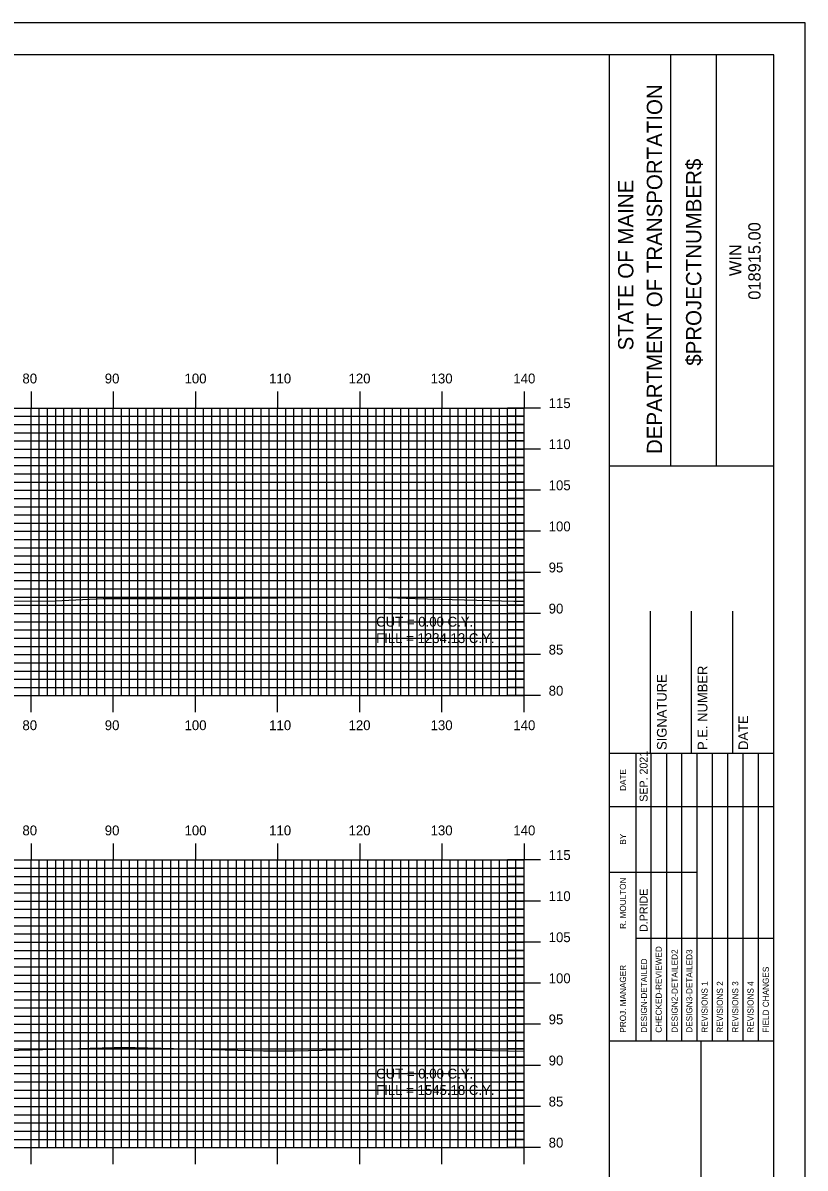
# Model space of a CAD drawing. Extents: x 879 to 1222, y -1658 to -1438.
# Drawn here: x 1123.7 to 1218.9, y -1577.1 to -1437.7 of the extents above; entities that cross this region are included whole.
import ezdxf

# ---------------------------------------------------------------- set-up
doc = ezdxf.new("R2010")
doc.units = 0
for name, color, linetype in [('BORDER', 7, 'Continuous'), ('D_Text_Standard', 7, 'Continuous'), ('H_V ANNOTATION', 7, 'Continuous'), ('MAJOR', 7, 'Continuous'), ('MINOR', 7, 'Continuous'), ('PLOT BOUNDARY', 7, 'Continuous'), ('S_Roadway_Centerline', 7, 'Continuous')]:
    doc.layers.add(name, color=color, linetype=linetype)

msp = doc.modelspace()

# ---------------------------------------------------------------- linework, layer by layer
at = {"layer": 'BORDER'}
for p, q in [((1195.05, -1651.6), (1195.05, -1441.6)), ((1202.5, -1491.61), (1202.5, -1441.61)), ((1208.09, -1491.61), (1208.09, -1441.61)), ((1195.05, -1491.62), (1215.05, -1491.62)), ((1200.05, -1526.6), (1200.05, -1509.3)), ((1205.05, -1526.6), (1205.05, -1509.3)), ((1210.05, -1526.6), (1210.05, -1509.3)), ((1195.05, -1526.6), (1215.05, -1526.6)), ((1195.05, -1561.6), (1215.05, -1561.6)), ((1206.23, -1631.6), (1206.23, -1561.6))]:
    msp.add_line(p, q, dxfattribs=at)
msp.add_lwpolyline([(895.05, -1651.6), (1215.05, -1651.6), (1215.05, -1441.6), (895.05, -1441.6)], close=True, dxfattribs=at)
for points in [[(1198.28, -1533.1), (1198.28, -1526.6)], [(1200.14, -1561.59), (1200.14, -1526.6)], [(1202.01, -1526.6), (1202.01, -1561.59)], [(1203.87, -1561.59), (1203.87, -1526.6)], [(1205.73, -1561.59), (1205.73, -1526.6)], [(1207.6, -1561.59), (1207.6, -1526.6)], [(1209.46, -1561.59), (1209.46, -1526.6)], [(1211.32, -1561.59), (1211.32, -1526.6)], [(1213.19, -1561.59), (1213.19, -1526.6)], [(1198.28, -1561.59), (1198.28, -1528.01)], [(1195.05, -1533.1), (1215.05, -1533.1)], [(1195.05, -1541.1), (1198.28, -1541.1)], [(1198.28, -1541.1), (1205.73, -1541.1)], [(1198.28, -1549.1), (1215.05, -1549.1)]]:
    msp.add_lwpolyline(points, dxfattribs=at)
at = {"layer": 'MAJOR'}
for p, q in [((1124.65, -1482.6), (1124.65, -1484.6)), ((1134.65, -1482.6), (1134.65, -1484.6)), ((1144.65, -1482.6), (1144.65, -1484.6)), ((1154.65, -1482.6), (1154.65, -1484.6)), ((1164.65, -1482.6), (1164.65, -1484.6)), ((1174.65, -1482.6), (1174.65, -1484.6)), ((1184.65, -1482.6), (1184.65, -1484.6)), ((904.65, -1484.6), (1184.65, -1484.6)), ((904.65, -1484.6), (1184.65, -1484.6)), ((1124.65, -1519.6), (1124.65, -1484.6)), ((1134.65, -1519.6), (1134.65, -1484.6)), ((1144.65, -1519.6), (1144.65, -1484.6)), ((1154.65, -1519.6), (1154.65, -1484.6)), ((1164.65, -1519.6), (1164.65, -1484.6)), ((1174.65, -1519.6), (1174.65, -1484.6)), ((1186.65, -1484.6), (1182.64, -1484.6)), ((1184.65, -1519.6), (1184.65, -1484.6)), ((1184.65, -1519.6), (1184.65, -1484.6)), ((904.65, -1489.6), (1184.65, -1489.6)), ((1186.65, -1489.6), (1182.64, -1489.6)), ((904.65, -1494.6), (1184.65, -1494.6)), ((1186.65, -1494.6), (1182.64, -1494.6)), ((904.65, -1499.6), (1184.65, -1499.6)), ((1186.65, -1499.6), (1182.64, -1499.6)), ((904.65, -1504.6), (1184.65, -1504.6)), ((1186.65, -1504.6), (1182.64, -1504.6)), ((904.65, -1509.6), (1184.65, -1509.6)), ((1186.65, -1509.6), (1182.64, -1509.6)), ((904.65, -1514.6), (1184.65, -1514.6)), ((1186.65, -1514.6), (1182.64, -1514.6)), ((904.65, -1519.6), (1184.65, -1519.6)), ((904.65, -1519.6), (1184.65, -1519.6)), ((1124.65, -1521.61), (1124.65, -1519.6)), ((1134.65, -1521.61), (1134.65, -1519.6)), ((1144.65, -1521.61), (1144.65, -1519.6)), ((1154.65, -1521.61), (1154.65, -1519.6)), ((1164.65, -1521.61), (1164.65, -1519.6)), ((1174.65, -1521.61), (1174.65, -1519.6)), ((1186.65, -1519.6), (1182.64, -1519.6)), ((1184.65, -1521.61), (1184.65, -1519.6)), ((1124.65, -1537.6), (1124.65, -1539.6)), ((1134.65, -1537.6), (1134.65, -1539.6)), ((1144.65, -1537.6), (1144.65, -1539.6)), ((1154.65, -1537.6), (1154.65, -1539.6)), ((1164.65, -1537.6), (1164.65, -1539.6)), ((1174.65, -1537.6), (1174.65, -1539.6)), ((1184.65, -1537.6), (1184.65, -1539.6)), ((904.65, -1539.6), (1184.65, -1539.6)), ((904.65, -1539.6), (1184.65, -1539.6)), ((1124.65, -1574.6), (1124.65, -1539.6)), ((1134.65, -1574.6), (1134.65, -1539.6)), ((1144.65, -1574.6), (1144.65, -1539.6)), ((1154.65, -1574.6), (1154.65, -1539.6)), ((1164.65, -1574.6), (1164.65, -1539.6)), ((1174.65, -1574.6), (1174.65, -1539.6)), ((1186.65, -1539.6), (1182.64, -1539.6)), ((1184.65, -1574.6), (1184.65, -1539.6)), ((1184.65, -1574.6), (1184.65, -1539.6)), ((904.65, -1544.6), (1184.65, -1544.6)), ((1186.65, -1544.6), (1182.64, -1544.6)), ((904.65, -1549.6), (1184.65, -1549.6)), ((1186.65, -1549.6), (1182.64, -1549.6)), ((904.65, -1554.6), (1184.65, -1554.6)), ((1186.65, -1554.6), (1182.64, -1554.6)), ((904.65, -1559.6), (1184.65, -1559.6)), ((1186.65, -1559.6), (1182.64, -1559.6)), ((904.65, -1564.6), (1184.65, -1564.6)), ((1186.65, -1564.6), (1182.64, -1564.6)), ((904.65, -1569.6), (1184.65, -1569.6)), ((1186.65, -1569.6), (1182.64, -1569.6)), ((904.65, -1574.6), (1184.65, -1574.6)), ((904.65, -1574.6), (1184.65, -1574.6)), ((1124.65, -1576.61), (1124.65, -1574.6)), ((1134.65, -1576.61), (1134.65, -1574.6)), ((1144.65, -1576.61), (1144.65, -1574.6)), ((1154.65, -1576.61), (1154.65, -1574.6)), ((1164.65, -1576.61), (1164.65, -1574.6)), ((1174.65, -1576.61), (1174.65, -1574.6)), ((1186.65, -1574.6), (1182.64, -1574.6)), ((1184.65, -1576.61), (1184.65, -1574.6))]:
    msp.add_line(p, q, dxfattribs=at)
at = {"layer": 'MINOR'}
for p, q in [((904.65, -1485.6), (1184.65, -1485.6)), ((1125.65, -1519.6), (1125.65, -1484.6)), ((1126.65, -1519.6), (1126.65, -1484.6)), ((1127.65, -1519.6), (1127.65, -1484.6)), ((1128.65, -1519.6), (1128.65, -1484.6)), ((1129.65, -1519.6), (1129.65, -1484.6)), ((1130.65, -1519.6), (1130.65, -1484.6)), ((1131.65, -1519.6), (1131.65, -1484.6)), ((1132.65, -1519.6), (1132.65, -1484.6)), ((1133.65, -1519.6), (1133.65, -1484.6)), ((1135.65, -1519.6), (1135.65, -1484.6)), ((1136.65, -1519.6), (1136.65, -1484.6)), ((1137.65, -1519.6), (1137.65, -1484.6)), ((1138.65, -1519.6), (1138.65, -1484.6)), ((1139.65, -1519.6), (1139.65, -1484.6)), ((1140.65, -1519.6), (1140.65, -1484.6)), ((1141.65, -1519.6), (1141.65, -1484.6)), ((1142.65, -1519.6), (1142.65, -1484.6)), ((1143.65, -1519.6), (1143.65, -1484.6)), ((1145.65, -1519.6), (1145.65, -1484.6)), ((1146.65, -1519.6), (1146.65, -1484.6)), ((1147.65, -1519.6), (1147.65, -1484.6)), ((1148.65, -1519.6), (1148.65, -1484.6)), ((1149.65, -1519.6), (1149.65, -1484.6)), ((1150.65, -1519.6), (1150.65, -1484.6)), ((1151.65, -1519.6), (1151.65, -1484.6)), ((1152.65, -1519.6), (1152.65, -1484.6)), ((1153.65, -1519.6), (1153.65, -1484.6)), ((1155.65, -1519.6), (1155.65, -1484.6)), ((1156.65, -1519.6), (1156.65, -1484.6)), ((1157.65, -1519.6), (1157.65, -1484.6)), ((1158.65, -1519.6), (1158.65, -1484.6)), ((1159.65, -1519.6), (1159.65, -1484.6)), ((1160.65, -1519.6), (1160.65, -1484.6)), ((1161.65, -1519.6), (1161.65, -1484.6)), ((1162.65, -1519.6), (1162.65, -1484.6)), ((1163.65, -1519.6), (1163.65, -1484.6)), ((1165.65, -1519.6), (1165.65, -1484.6)), ((1166.65, -1519.6), (1166.65, -1484.6)), ((1167.65, -1519.6), (1167.65, -1484.6)), ((1168.65, -1519.6), (1168.65, -1484.6)), ((1169.65, -1519.6), (1169.65, -1484.6)), ((1170.65, -1519.6), (1170.65, -1484.6)), ((1171.65, -1519.6), (1171.65, -1484.6)), ((1172.65, -1519.6), (1172.65, -1484.6)), ((1173.65, -1519.6), (1173.65, -1484.6)), ((1175.65, -1519.6), (1175.65, -1484.6)), ((1176.65, -1519.6), (1176.65, -1484.6)), ((1177.65, -1519.6), (1177.65, -1484.6)), ((1178.65, -1519.6), (1178.65, -1484.6)), ((1179.65, -1519.6), (1179.65, -1484.6)), ((1180.65, -1519.6), (1180.65, -1484.6)), ((1181.65, -1519.6), (1181.65, -1484.6)), ((1184.65, -1485.6), (1182.64, -1485.6)), ((1182.65, -1519.6), (1182.65, -1484.6)), ((1183.65, -1519.6), (1183.65, -1484.6)), ((904.65, -1486.6), (1184.65, -1486.6)), ((1184.65, -1486.6), (1182.64, -1486.6)), ((904.65, -1487.6), (1184.65, -1487.6)), ((1184.65, -1487.6), (1182.64, -1487.6)), ((904.65, -1488.6), (1184.65, -1488.6)), ((1184.65, -1488.6), (1182.64, -1488.6)), ((904.65, -1490.6), (1184.65, -1490.6)), ((1184.65, -1490.6), (1182.64, -1490.6)), ((904.65, -1491.6), (1184.65, -1491.6)), ((904.65, -1492.6), (1184.65, -1492.6)), ((1184.65, -1491.6), (1182.64, -1491.6)), ((1184.65, -1492.6), (1182.64, -1492.6)), ((904.65, -1493.6), (1184.65, -1493.6)), ((1184.65, -1493.6), (1182.64, -1493.6)), ((904.65, -1495.6), (1184.65, -1495.6)), ((904.65, -1496.6), (1184.65, -1496.6)), ((1184.65, -1495.6), (1182.64, -1495.6)), ((1184.65, -1496.6), (1182.64, -1496.6)), ((904.65, -1497.6), (1184.65, -1497.6)), ((1184.65, -1497.6), (1182.64, -1497.6)), ((904.65, -1498.6), (1184.65, -1498.6)), ((1184.65, -1498.6), (1182.64, -1498.6)), ((904.65, -1500.6), (1184.65, -1500.6)), ((1184.65, -1500.6), (1182.64, -1500.6)), ((904.65, -1501.6), (1184.65, -1501.6)), ((1184.65, -1501.6), (1182.64, -1501.6)), ((904.65, -1502.6), (1184.65, -1502.6)), ((904.65, -1503.6), (1184.65, -1503.6)), ((1184.65, -1502.6), (1182.64, -1502.6)), ((1184.65, -1503.6), (1182.64, -1503.6)), ((904.65, -1505.6), (1184.65, -1505.6)), ((904.65, -1506.6), (1184.65, -1506.6)), ((1184.65, -1505.6), (1182.64, -1505.6)), ((1184.65, -1506.6), (1182.64, -1506.6)), ((904.65, -1507.6), (1184.65, -1507.6)), ((1184.65, -1507.6), (1182.64, -1507.6)), ((904.65, -1508.6), (1184.65, -1508.6)), ((1184.65, -1508.6), (1182.64, -1508.6)), ((904.65, -1510.6), (1184.65, -1510.6)), ((1184.65, -1510.6), (1182.64, -1510.6)), ((904.65, -1511.6), (1184.65, -1511.6)), ((1184.65, -1511.6), (1182.64, -1511.6)), ((904.65, -1512.6), (1184.65, -1512.6)), ((904.65, -1513.6), (1184.65, -1513.6)), ((1184.65, -1512.6), (1182.64, -1512.6)), ((1184.65, -1513.6), (1182.64, -1513.6)), ((904.65, -1515.6), (1184.65, -1515.6)), ((1184.65, -1515.6), (1182.64, -1515.6)), ((904.65, -1516.6), (1184.65, -1516.6)), ((904.65, -1517.6), (1184.65, -1517.6)), ((1184.65, -1516.6), (1182.64, -1516.6)), ((1184.65, -1517.6), (1182.64, -1517.6)), ((904.65, -1518.6), (1184.65, -1518.6)), ((1184.65, -1518.6), (1182.64, -1518.6)), ((1125.65, -1574.6), (1125.65, -1539.6)), ((1126.65, -1574.6), (1126.65, -1539.6)), ((1127.65, -1574.6), (1127.65, -1539.6)), ((1128.65, -1574.6), (1128.65, -1539.6)), ((1129.65, -1574.6), (1129.65, -1539.6)), ((1130.65, -1574.6), (1130.65, -1539.6)), ((1131.65, -1574.6), (1131.65, -1539.6)), ((1132.65, -1574.6), (1132.65, -1539.6)), ((1133.65, -1574.6), (1133.65, -1539.6)), ((1135.65, -1574.6), (1135.65, -1539.6)), ((1136.65, -1574.6), (1136.65, -1539.6)), ((1137.65, -1574.6), (1137.65, -1539.6)), ((1138.65, -1574.6), (1138.65, -1539.6)), ((1139.65, -1574.6), (1139.65, -1539.6)), ((1140.65, -1574.6), (1140.65, -1539.6)), ((1141.65, -1574.6), (1141.65, -1539.6)), ((1142.65, -1574.6), (1142.65, -1539.6)), ((1143.65, -1574.6), (1143.65, -1539.6)), ((1145.65, -1574.6), (1145.65, -1539.6)), ((1146.65, -1574.6), (1146.65, -1539.6)), ((1147.65, -1574.6), (1147.65, -1539.6)), ((1148.65, -1574.6), (1148.65, -1539.6)), ((1149.65, -1574.6), (1149.65, -1539.6)), ((1150.65, -1574.6), (1150.65, -1539.6)), ((1151.65, -1574.6), (1151.65, -1539.6)), ((1152.65, -1574.6), (1152.65, -1539.6)), ((1153.65, -1574.6), (1153.65, -1539.6)), ((1155.65, -1574.6), (1155.65, -1539.6)), ((1156.65, -1574.6), (1156.65, -1539.6)), ((1157.65, -1574.6), (1157.65, -1539.6)), ((1158.65, -1574.6), (1158.65, -1539.6)), ((1159.65, -1574.6), (1159.65, -1539.6)), ((1160.65, -1574.6), (1160.65, -1539.6)), ((1161.65, -1574.6), (1161.65, -1539.6)), ((1162.65, -1574.6), (1162.65, -1539.6)), ((1163.65, -1574.6), (1163.65, -1539.6)), ((1165.65, -1574.6), (1165.65, -1539.6)), ((1166.65, -1574.6), (1166.65, -1539.6)), ((1167.65, -1574.6), (1167.65, -1539.6)), ((1168.65, -1574.6), (1168.65, -1539.6)), ((1169.65, -1574.6), (1169.65, -1539.6)), ((1170.65, -1574.6), (1170.65, -1539.6)), ((1171.65, -1574.6), (1171.65, -1539.6)), ((1172.65, -1574.6), (1172.65, -1539.6)), ((1173.65, -1574.6), (1173.65, -1539.6)), ((1175.65, -1574.6), (1175.65, -1539.6)), ((1176.65, -1574.6), (1176.65, -1539.6)), ((1177.65, -1574.6), (1177.65, -1539.6)), ((1178.65, -1574.6), (1178.65, -1539.6)), ((1179.65, -1574.6), (1179.65, -1539.6)), ((1180.65, -1574.6), (1180.65, -1539.6)), ((1181.65, -1574.6), (1181.65, -1539.6)), ((1182.65, -1574.6), (1182.65, -1539.6)), ((1183.65, -1574.6), (1183.65, -1539.6)), ((904.65, -1540.6), (1184.65, -1540.6)), ((1184.65, -1540.6), (1182.64, -1540.6)), ((904.65, -1541.6), (1184.65, -1541.6)), ((904.65, -1542.6), (1184.65, -1542.6)), ((1184.65, -1541.6), (1182.64, -1541.6)), ((1184.65, -1542.6), (1182.64, -1542.6)), ((904.65, -1543.6), (1184.65, -1543.6)), ((1184.65, -1543.6), (1182.64, -1543.6)), ((904.65, -1545.6), (1184.65, -1545.6)), ((1184.65, -1545.6), (1182.64, -1545.6)), ((904.65, -1546.6), (1184.65, -1546.6)), ((1184.65, -1546.6), (1182.64, -1546.6)), ((904.65, -1547.6), (1184.65, -1547.6)), ((1184.65, -1547.6), (1182.64, -1547.6)), ((904.65, -1548.6), (1184.65, -1548.6)), ((1184.65, -1548.6), (1182.64, -1548.6)), ((904.65, -1550.6), (1184.65, -1550.6)), ((1184.65, -1550.6), (1182.64, -1550.6)), ((904.65, -1551.6), (1184.65, -1551.6)), ((904.65, -1552.6), (1184.65, -1552.6)), ((1184.65, -1551.6), (1182.64, -1551.6)), ((1184.65, -1552.6), (1182.64, -1552.6)), ((904.65, -1553.6), (1184.65, -1553.6)), ((1184.65, -1553.6), (1182.64, -1553.6)), ((904.65, -1555.6), (1184.65, -1555.6)), ((904.65, -1556.6), (1184.65, -1556.6)), ((1184.65, -1555.6), (1182.64, -1555.6)), ((1184.65, -1556.6), (1182.64, -1556.6)), ((904.65, -1557.6), (1184.65, -1557.6)), ((1184.65, -1557.6), (1182.64, -1557.6)), ((904.65, -1558.6), (1184.65, -1558.6)), ((1184.65, -1558.6), (1182.64, -1558.6)), ((904.65, -1560.6), (1184.65, -1560.6)), ((1184.65, -1560.6), (1182.64, -1560.6)), ((904.65, -1561.6), (1184.65, -1561.6)), ((1184.65, -1561.6), (1182.64, -1561.6)), ((904.65, -1562.6), (1184.65, -1562.6)), ((904.65, -1563.6), (1184.65, -1563.6)), ((1184.65, -1562.6), (1182.64, -1562.6)), ((1184.65, -1563.6), (1182.64, -1563.6)), ((904.65, -1565.6), (1184.65, -1565.6)), ((1184.65, -1565.6), (1182.64, -1565.6)), ((904.65, -1566.6), (1184.65, -1566.6)), ((904.65, -1567.6), (1184.65, -1567.6)), ((1184.65, -1566.6), (1182.64, -1566.6)), ((1184.65, -1567.6), (1182.64, -1567.6)), ((904.65, -1568.6), (1184.65, -1568.6)), ((1184.65, -1568.6), (1182.64, -1568.6)), ((904.65, -1570.6), (1184.65, -1570.6)), ((1184.65, -1570.6), (1182.64, -1570.6)), ((904.65, -1571.6), (1184.65, -1571.6)), ((1184.65, -1571.6), (1182.64, -1571.6)), ((904.65, -1572.6), (1184.65, -1572.6)), ((1184.65, -1572.6), (1182.64, -1572.6)), ((904.65, -1573.6), (1184.65, -1573.6)), ((1184.65, -1573.6), (1182.64, -1573.6))]:
    msp.add_line(p, q, dxfattribs=at)
at = {"layer": 'PLOT BOUNDARY'}
msp.add_lwpolyline([(878.86, -1657.72), (1218.86, -1657.72), (1218.86, -1437.72), (878.86, -1437.72)], close=True, dxfattribs=at)
at = {"layer": 'S_Roadway_Centerline'}
for points in [[(1029.58, -1508.74), (1035.48, -1509.02), (1041.11, -1508.92), (1051.86, -1508.83), (1060.02, -1508.77), (1068.21, -1508.6), (1075.2, -1508.53), (1084.19, -1508.54), (1092.9, -1508.03), (1100.62, -1507.97), (1108.45, -1508.03), (1117.43, -1508.14), (1127.6, -1508.04), (1133.42, -1507.76), (1144.55, -1507.77), (1150.5, -1507.75), (1162.89, -1507.6), (1167.05, -1507.63), (1171.39, -1507.76), (1183.39, -1508.09), (1184.65, -1508.08)], [(1029.13, -1563.37), (1035.94, -1563.09), (1042.32, -1563.11), (1053.45, -1563.11), (1057.29, -1563.12), (1084.22, -1563.09), (1086.31, -1563.07), (1088.39, -1563.09), (1101.66, -1563.1), (1108.17, -1563), (1117.46, -1562.86), (1118.73, -1562.85), (1134.78, -1562.43), (1135.95, -1562.41), (1137.31, -1562.42), (1152.94, -1562.84), (1156.79, -1562.81), (1168.28, -1562.55), (1174.99, -1562.68), (1184.65, -1562.88)]]:
    msp.add_lwpolyline(points, dxfattribs=at)

# ---------------------------------------------------------------- texts
at = {"layer": 'BORDER'}
for s, height, p in [('DEPARTMENT OF TRANSPORTATION', 1.8635, (1201.46, -1490.19)), ('$PROJECTNUMBER$', 1.8635, (1206.23, -1479.45)), ('STATE OF MAINE', 1.8635, (1197.96, -1477.58)), ('018915.00', 1.491, (1213.44, -1471.41)), ('WIN', 1.491, (1211.12, -1468.54)), ('P.E. NUMBER', 1.1811, (1206.97, -1526.21)), ('SIGNATURE', 1.181, (1202.01, -1526.21)), ('DATE', 1.181, (1211.93, -1526.21)), ('SEP. 2021', 0.969, (1199.69, -1532.51)), ('DATE', 0.743, (1197.06, -1531.19)), ('BY', 0.743, (1197.06, -1537.73)), ('R. MOULTON', 0.745, (1197.06, -1547.99)), ('D.PRIDE', 0.969, (1199.69, -1548.35)), ('CHECKED-REVIEWED', 0.7455, (1201.41, -1560.62)), ('DESIGN2-DETAILED2', 0.7455, (1203.35, -1560.62)), ('DESIGN3-DETAILED3', 0.7455, (1205.14, -1560.62)), ('PROJ. MANAGER', 0.7455, (1197.06, -1560.62)), ('DESIGN-DETAILED', 0.7455, (1199.62, -1560.62)), ('FIELD CHANGES', 0.7455, (1214.45, -1560.62)), ('REVISIONS 1', 0.7455, (1207, -1560.62)), ('REVISIONS 2', 0.7455, (1208.86, -1560.62)), ('REVISIONS 3', 0.7455, (1210.73, -1560.62)), ('REVISIONS 4', 0.7455, (1212.59, -1560.62))]:
    msp.add_text(s, height=height, rotation=90, dxfattribs=at).set_placement(p)
at = {"layer": 'D_Text_Standard'}
for s, p in [('CUT = 0.00 C.Y.', (1166.65, -1511.2)), ('FILL = 1234.13 C.Y.', (1166.65, -1513.2)), ('CUT = 0.00 C.Y.', (1166.65, -1566.2)), ('FILL = 1545.18 C.Y.', (1166.65, -1568.2))]:
    msp.add_text(s, height=1.2, dxfattribs=at).set_placement(p)
at = {"layer": 'H_V ANNOTATION'}
for s, p in [('80', (1123.6, -1481.6)), ('90', (1133.62, -1481.6)), ('100', (1143.33, -1481.6)), ('110', (1153.63, -1481.6)), ('120', (1163.29, -1481.6)), ('130', (1173.28, -1481.6)), ('140', (1183.35, -1481.6)), ('115', (1187.65, -1484.6)), ('110', (1187.65, -1489.6)), ('105', (1187.65, -1494.6)), ('100', (1187.65, -1499.6)), ('95', (1187.65, -1504.6)), ('90', (1187.65, -1509.6)), ('85', (1187.65, -1514.6)), ('80', (1187.65, -1519.6)), ('80', (1123.6, -1523.8)), ('90', (1133.62, -1523.8)), ('100', (1143.33, -1523.8)), ('110', (1153.63, -1523.8)), ('120', (1163.29, -1523.8)), ('130', (1173.28, -1523.8)), ('140', (1183.35, -1523.8)), ('80', (1123.6, -1536.6)), ('90', (1133.62, -1536.6)), ('100', (1143.33, -1536.6)), ('110', (1153.63, -1536.6)), ('120', (1163.29, -1536.6)), ('130', (1173.28, -1536.6)), ('140', (1183.35, -1536.6)), ('115', (1187.65, -1539.6)), ('110', (1187.65, -1544.6)), ('105', (1187.65, -1549.6)), ('100', (1187.65, -1554.6)), ('95', (1187.65, -1559.6)), ('90', (1187.65, -1564.6)), ('85', (1187.65, -1569.6)), ('80', (1187.65, -1574.6))]:
    msp.add_text(s, height=1.2, dxfattribs=at).set_placement(p)

doc.saveas('drawing.dxf')
